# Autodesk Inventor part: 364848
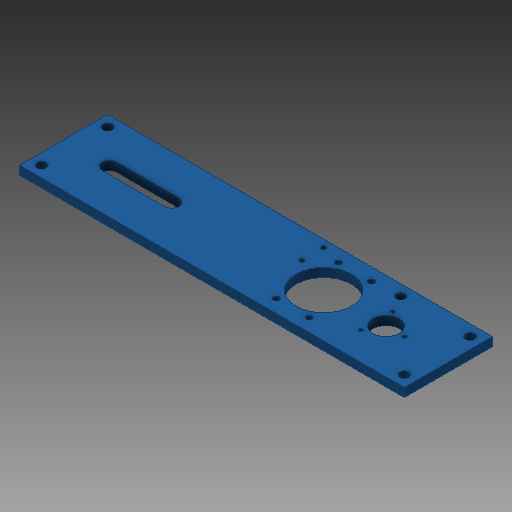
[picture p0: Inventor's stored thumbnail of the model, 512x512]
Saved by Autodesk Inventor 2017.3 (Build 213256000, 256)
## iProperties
Company: Mayer & Müller AG Schaltgeräte
Created: 2017-06
Part Number: 364848
Material: 1.0120
Document SubType Name: Modeling
Designer: I.Baliuc
Manufacturer: Standard
Standards Organization: Custom
Description: Seitenteil, Trenner
Density: 7.85 g/cm^3
Appearance: RAL 5012 Lichtblau
HalbzeugNorm: DIN 174
Zweck: Antriebseite: Motor-Standard
Abmessung: Fl. 120x12-525
Kopiert_von_Autor: CH
Kopie_erstellt_am: 2017-06-09T10:09:37
Kopiert_von_Datei: D:\Inventor-Tools Tutorial\Bauteile\3\36\364846.ipt
Kopie_Zieldatei: D:\Inventor-Tools Tutorial\Bauteile\3\36\364848.ipt
dX*dY*dZ: 525 x 120 x 12
Flaeche: 136259
Volumen: 651408
Author: CH
Keywords: 380125
Revision Number: 364846
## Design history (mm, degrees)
sketch "Skizze2"
  geometry: L1 (-170, 60)-(355, 60); L2 (355, 60)-(355, -60); L3 (355, -60)-(-170, -60); L4 (-170, -60)-(-170, 60); L5 (-222.5, 0)-(512.5, 0) reference; L6 (0, -72)-(0, 96) reference; L7 (292.5, 10)-(207.5, 10); L8 (207.5, -10)-(292.5, -10); C1 r 38 at (0, 0); A1 r 10 centre (292.5, 0) between (292.5, -10) and (292.5, 10); A2 r 10 centre (207.5, 0) between (207.5, 10) and (207.5, -10)
  constraints: 12 end point, 4 point on circle, 4 point on line, 3 centre point, 3 parallel, 2 tangent, 1 horizontal, 1 perpendicular, 2 other
  dimensions: "d4" = 170 distance between parallel lines of L4 L6; "d5" = 525 distance of L1.start L1.end; "d6" = 120 distance of L3.end L1.start; "d7" = 76 diameter of C1; "d8" = 85 distance of A2.centre A1.centre; "d9" = 20 distance between parallel lines of L7 L8; "d10" = 62.5 distance from line of L2 A1.centre
extrude "Extrusion2" new body sketch "Skizze2" distance "d11" = 12; taper "d12" = 0 deg
sketch "Skizze3"
  geometry: L1 (355, 60)-(355, -60) reference; L2 (-170, -60)-(-170, 60) reference; L3 (-222.5, 0)-(512.5, 0) reference; 4 further points
  constraints: 2 symmetric about line
  dimensions: "d13" = 90 distance of point (-155, -45) point (-155, 45); "d14" = 15 distance from line of point (-155, 45) L2; "d15" = 90 distance of point (340, -45) point (340, 45) (= d13); "d16" = 15 distance from line of point (340, 45) L1 (= d14)
hole "Bohrung_Ø13" sketch "Skizze3" at (-155, 45), (-155, -45), (340, -45), (340, 45) diameter "d17" = 13; stored, may be unused: countersink angle "d21" = 90 deg, drill point angle "d23" = 118 deg; dims "d18" = 6, "d19" = 4, "d20" = 2, "d22" = 8
sketch "Skizze4"
  geometry: L1 (-222.5, 0)-(512.5, 0) reference; L2 (0, -72)-(0, 96) reference; 4 further points
  constraints: 3 symmetric about line
  dimensions: "d24" = 85 distance of point (22.5, -42.5) point (22.5, 42.5); "d25" = 45 distance of point (-22.5, 42.5) point (22.5, 42.5)
hole "Bohrung2" sketch "Skizze4" at (22.5, 42.5), (22.5, -42.5), (-22.5, -42.5), (-22.5, 42.5) diameter "d26" = 16.5; stored, may be unused: countersink angle "d30" = 90 deg, drill point angle "d32" = 0 deg; dims "d27" = 6, "d28" = 16.5, "d29" = 0.4, "d31" = 0.7
sketch "Skizze5"
  geometry: C1 r 8.25 at (0, 0) reference; C2 r 8.25 at (0, -85) reference; C3 r 8.25 at (45, -85) reference; C4 r 8.25 at (45, 0) reference; 4 further points
  constraints: 4 coincident
hole "Bohrung3" sketch "Skizze5" at (0, 0), (45, 0), (45, -85), (0, -85) diameter "d33" = 8.4; stored, may be unused: countersink angle "d37" = 90 deg, drill point angle "d39" = 118 deg; dims "d34" = 6, "d35" = 16.5 (= d26), "d36" = 2, "d38" = 8
sketch "Skizze6" dims "d56" = 10
  geometry: L1 (-170, -60)-(-170, 60) reference; L2 (-222.5, 0)-(512.5, 0) reference; C1 r 38 at (0, 0) reference; 2 further points
  constraints: 1 vertical, 1 other
  dimensions: "d49" = 50 horizontal distance of point (50, 20) C1.centre; "d50" = 20 vertical distance of C1.centre point (50, 20); "d53" = 30 distance of point (50, 20) point (50, 50)
hole "Bohrung_M8" sketch "Skizze6" at (50, 20), (50, 50) diameter "d42" = 6.647; stored, may be unused: countersink angle "d46" = 90 deg, drill point angle "d48" = 118 deg; dims "d43" = 6, "d44" = 4, "d45" = 2, "d47" = 8
sketch "Skizze7"
  geometry: L1 (0, -72)-(0, 96) reference; L2 (-222.5, 0)-(512.5, 0) reference; 1 further point
  constraints: 1 point on line
  dimensions: "d58" = 85 distance from line of L1 point (-85, 0)
hole "Bohrung_Ø36" sketch "Skizze7" at (-85, 0) diameter "d59" = 36; stored, may be unused: countersink angle "d63" = 90 deg, drill point angle "d65" = 118 deg; dims "d60" = 6, "d61" = 4, "d62" = 2, "d64" = 8
sketch "Skizze8"
  geometry: L1 (-222.5, 0)-(512.5, 0) reference; C1 r 18 at (-85, 0) reference; 3 further points
  constraints: 1 point on line, 4 other
  dimensions: "d66" = 25 distance of point (-110, 0) C1.centre; "d69" = 360 deg dimension on C1.centre point (-110, 0) (derived)
hole "Bohrung_Ø5.5" sketch "Skizze8" at (-110, 0), (-72.5, -21.651), (-72.5, 21.651) diameter "d71" = 5.5; stored, may be unused: countersink angle "d75" = 90 deg, drill point angle "d77" = 118 deg; dims "d72" = 6, "d73" = 4, "d74" = 2, "d76" = 8
sketch "Skizze9"
  geometry: C1 r 18 at (-85, 0) reference; 1 further point
  dimensions: "d78" = 25 horizontal distance of point (-60, 45) C1.centre; "d79" = 45 vertical distance of C1.centre point (-60, 45)
hole "Bohrung_Ø12" sketch "Skizze9" at (-60, 45) diameter "d80" = 12; stored, may be unused: countersink angle "d84" = 90 deg, drill point angle "d86" = 118 deg; dims "d81" = 6, "d82" = 4, "d83" = 2, "d85" = 8
sketch "Skizze10" dims "d96" = 10
  geometry: L1 (355, 60)-(355, -60) reference; L2 (355, -60)-(-170, -60) reference; 4 further points
  constraints: 1 horizontal, 2 other
  dimensions: "d87" = 15 distance from line of L2 point (274, -45); "d88" = 81 distance from line of point (274, -45) L1; "d89" = 30 distance of point (274, -45) point (244, -45); "d90" = 15 distance from line of L2 point (244, -45) (= d87); "d93" = 18 distance of point (274, -45) point (256, -45)
hole "Bohrung_Ø2" sketch "Skizze10" at (274, -45), (244, -45), (256, -45), (226, -45) diameter "d98" = 2; stored, may be unused: countersink angle "d102" = 90 deg, drill point angle "d104" = 118 deg; dims "d99" = 6, "d100" = 4, "d101" = 2, "d103" = 8
node "Schwerpunkt_1"
node "Volumenkörper1"
node "Volumenkörpern"
node "Oberflächenkörpern"
node "Projizierte Kontur1"
